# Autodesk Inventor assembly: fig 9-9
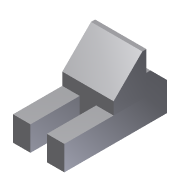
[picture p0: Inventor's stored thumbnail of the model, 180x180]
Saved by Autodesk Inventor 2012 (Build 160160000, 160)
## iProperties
Shininess: 64.0
Length Units: 11269
Angle Units: 11279
Time Units: 11290
Mass Units: 11283
Length Display Precision: 3
Angle Display Precision: 2
Created: 2002-01
Part Number: fig 9-9
Document SubType Name: Assembly
Designer: ***
Density: 0.0
Volumn: 0.0
Area: 0.0
PropertySet Name: Model Information
Control State: 0
Master: False
Checked Out: False
Author: ***
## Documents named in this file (3)
- C:\Users\CadCim\Documents\SAILESH\inventor-2011-fact-prt\c09_inv_2011-prt\c09_inv_2012_prt\fig 9-9.iam
- C:\Users\CadCim\Documents\SAILESH\inventor-2011-fact-prt\c09_inv_2011-prt\c09_inv_2012_prt\Part3.ipt
- C:\Users\CadCim\Documents\SAILESH\inventor-2011-fact-prt\c09_inv_2011-prt\c09_inv_2012_prt\Part4.ipt
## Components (2 placed, 2 different names)
1. Part3:1 — Mate:1
2. Part4:1 — Mate:1
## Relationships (1: Mate 1)
- Mate:1: Part3:1 ↔ Part4:1
